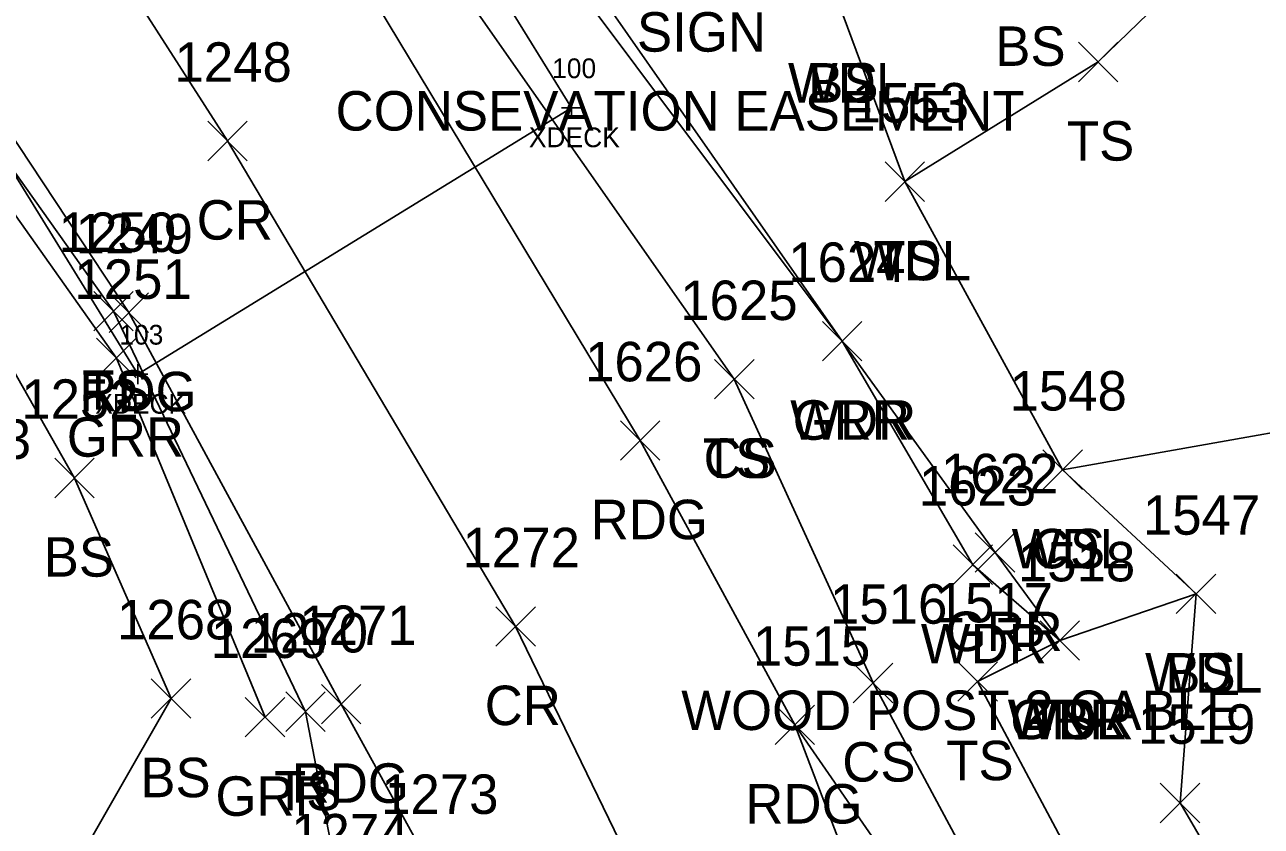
# Model space of a CAD drawing. Extents: x 1469310 to 1475157, y 493997 to 498873.
# Drawn here: x 1469560.4 to 1469623, y 498537.1 to 498577.7 of the extents above; entities that cross this region are included whole.
import ezdxf

# ---------------------------------------------------------------- set-up
doc = ezdxf.new("R2010")
doc.units = 0
for name, color, linetype in [('B_A', 7, 'Continuous'), ('B_I', 7, 'Continuous'), ('B_TIC', 7, 'Continuous'), ('BELB', 7, 'Continuous'), ('L_A', 7, 'Continuous'), ('L_I', 7, 'Continuous'), ('L_TIC', 7, 'Continuous'), ('LAWA', 7, 'Continuous'), ('LELB', 7, 'Continuous'), ('P_A', 7, 'Continuous'), ('P_I', 7, 'Continuous'), ('P_TIC', 7, 'Continuous'), ('PEU', 7, 'Continuous'), ('PRC', 7, 'Continuous'), ('R_A', 7, 'Continuous'), ('R_C', 7, 'Continuous'), ('R_I', 7, 'Continuous'), ('R_TIC', 7, 'Continuous'), ('RGR', 7, 'Continuous'), ('S_A', 7, 'Continuous'), ('S_C', 7, 'Continuous')]:
    doc.layers.add(name, color=color, linetype=linetype)

msp = doc.modelspace()

# ---------------------------------------------------------------- linework, layer by layer
at = {"layer": 'B_TIC'}
for p, q in [((1469588.088, 498573.469), (1469588.164, 498573.469)), ((1469566.108, 498559.964), (1469566.184, 498559.964))]:
    msp.add_line(p, q, dxfattribs=at)
for points in [[(1469587.585, 498573.469), (1469588.585, 498573.469)], [(1469588.085, 498572.969), (1469588.085, 498573.969)], [(1469566.105, 498559.464), (1469566.105, 498560.465)], [(1469565.605, 498559.964), (1469566.605, 498559.964)]]:
    msp.add_lwpolyline(points, dxfattribs=at)
at = {"layer": 'BELB'}
msp.add_lwpolyline([(1469588.085, 498573.469), (1469568.345, 498605.383), (1469546.47, 498591.781), (1469566.105, 498559.964), (1469588.085, 498573.469)], dxfattribs=at)
at = {"layer": 'L_TIC'}
for points in [[(1469613.784, 498574.789), (1469615.784, 498576.789)], [(1469615.784, 498574.789), (1469613.784, 498576.789)], [(1469603.978, 498568.723), (1469605.978, 498570.723)], [(1469605.978, 498568.723), (1469603.978, 498570.723)], [(1469603.978, 498568.723), (1469605.978, 498570.723)], [(1469605.978, 498568.723), (1469603.978, 498570.723)], [(1469563.878, 498562.16), (1469565.878, 498564.16)], [(1469565.878, 498562.16), (1469563.878, 498564.16)], [(1469600.808, 498560.641), (1469602.808, 498562.641)], [(1469602.808, 498560.641), (1469600.808, 498562.641)], [(1469595.337, 498558.709), (1469597.337, 498560.709)], [(1469597.337, 498558.709), (1469595.337, 498560.709)], [(1469595.337, 498558.709), (1469597.337, 498560.709)], [(1469597.337, 498558.709), (1469595.337, 498560.709)], [(1469611.977, 498554.124), (1469613.977, 498556.124)], [(1469613.977, 498554.124), (1469611.977, 498556.124)], [(1469611.977, 498554.124), (1469613.977, 498556.124)], [(1469613.977, 498554.124), (1469611.977, 498556.124)], [(1469561.893, 498553.703), (1469563.893, 498555.703)], [(1469563.893, 498553.703), (1469561.893, 498555.703)], [(1469607.427, 498549.309), (1469609.427, 498551.309)], [(1469609.427, 498549.309), (1469607.427, 498551.309)], [(1469618.738, 498547.83), (1469620.738, 498549.83)], [(1469620.738, 498547.83), (1469618.738, 498549.83)], [(1469618.738, 498547.83), (1469620.738, 498549.83)], [(1469620.738, 498547.83), (1469618.738, 498549.83)], [(1469611.833, 498545.464), (1469613.833, 498547.464)], [(1469613.833, 498545.464), (1469611.833, 498547.464)], [(1469611.833, 498545.464), (1469613.833, 498547.464)], [(1469613.833, 498545.464), (1469611.833, 498547.464)], [(1469611.833, 498545.464), (1469613.833, 498547.464)], [(1469613.833, 498545.464), (1469611.833, 498547.464)], [(1469602.368, 498543.316), (1469604.368, 498545.316)], [(1469604.368, 498543.316), (1469602.368, 498545.316)], [(1469607.669, 498543.385), (1469609.669, 498545.385)], [(1469609.669, 498543.385), (1469607.669, 498545.385)], [(1469566.788, 498542.524), (1469568.788, 498544.524)], [(1469568.788, 498542.524), (1469566.788, 498544.524)], [(1469573.599, 498541.858), (1469575.599, 498543.858)], [(1469575.599, 498541.858), (1469573.599, 498543.858)], [(1469617.927, 498537.232), (1469619.927, 498539.232)], [(1469619.927, 498537.232), (1469617.927, 498539.232)]]:
    msp.add_lwpolyline(points, dxfattribs=at)
at = {"layer": 'LAWA'}
for points in [[(1469612.833, 498546.464), (1469619.738, 498548.83), (1469612.977, 498555.124), (1469604.978, 498569.723), (1469601.64, 498578.733), (1469597.441, 498587.632), (1469591.889, 498597.878), (1469577.982, 498615.263), (1469573.01, 498624.242), (1469561.449, 498616.788)], [(1469612.833, 498546.464), (1469608.427, 498550.309), (1469601.808, 498561.641), (1469582.15, 498589.77), (1469568.417, 498610.17), (1469561.449, 498616.788)]]:
    msp.add_lwpolyline(points, dxfattribs=at)
at = {"layer": 'LELB'}
for points in [[(1469596.337, 498559.709), (1469578.349, 498585.399), (1469563.744, 498607.627), (1469555.371, 498620.368), (1469550.821, 498626.646), (1469541.68, 498637.319), (1469517.52, 498662.002), (1469494.243, 498687.266), (1469477.199, 498705.84), (1469448.358, 498735.299), (1469427.592, 498756.343), (1469413.618, 498771.296), (1469390.023, 498797.181), (1469364.143, 498823.885)], [(1469416.823, 498734.314), (1469446.326, 498703.097), (1469470.885, 498677.648), (1469509.281, 498636.708), (1469524.422, 498615.805), (1469544.375, 498592.02), (1469564.878, 498563.16), (1469574.599, 498542.858), (1469576.567, 498532.675), (1469562.977, 498525.948), (1469548.2, 498517.369), (1469540.614, 498511.222), (1469554.066, 498484.991), (1469566.508, 498459.59)], [(1469413.419, 498730.944), (1469442.517, 498698.703), (1469468.453, 498674.773), (1469500.535, 498635.821), (1469519.003, 498614.534), (1469533.172, 498594.862), (1469544.52, 498587.119), (1469562.893, 498554.703), (1469567.788, 498543.524), (1469559.261, 498528.602), (1469545.395, 498521.66), (1469536.791, 498513.026)], [(1469812.464, 498502.377), (1469771.643, 498507.322), (1469742.885, 498510.086), (1469696.566, 498535.255), (1469676.255, 498550.532), (1469652.996, 498571.738), (1469634.36, 498584.722), (1469625.46, 498586.142), (1469614.784, 498575.789), (1469604.978, 498569.723)], [(1469810.96, 498484.608), (1469774.316, 498494.217), (1469741.099, 498505.67), (1469693.032, 498528.464), (1469673.62, 498546.033), (1469647.104, 498565.825), (1469633.561, 498558.766), (1469612.977, 498555.124)], [(1469633.096, 498503.601), (1469614.184, 498524.16), (1469603.368, 498544.316), (1469596.337, 498559.709)], [(1469788.816, 498394.717), (1469772.488, 498406.102), (1469747.629, 498424.648), (1469713.944, 498449.335), (1469681.325, 498467.824), (1469654.974, 498486.974), (1469638.094, 498508.736), (1469624.13, 498529.309), (1469618.927, 498538.232), (1469619.738, 498548.83)], [(1469787.64, 498392.56), (1469771.327, 498404.285), (1469746.147, 498422.386), (1469712.154, 498445.439), (1469680.508, 498465.063), (1469652.746, 498484.347), (1469633.096, 498503.601), (1469618.233, 498526.441), (1469608.669, 498544.385), (1469612.833, 498546.464)]]:
    msp.add_lwpolyline(points, dxfattribs=at)
at = {"layer": 'P_TIC'}
for points in [[(1469569.656, 498570.785), (1469571.656, 498572.785)], [(1469571.656, 498570.785), (1469569.656, 498572.785)], [(1469564.651, 498562.085), (1469566.651, 498564.085)], [(1469566.651, 498562.085), (1469564.651, 498564.085)], [(1469590.57, 498555.602), (1469592.57, 498557.602)], [(1469592.57, 498555.602), (1469590.57, 498557.602)], [(1469584.254, 498546.179), (1469586.254, 498548.179)], [(1469586.254, 498546.179), (1469584.254, 498548.179)], [(1469575.412, 498542.24), (1469577.412, 498544.24)], [(1469577.412, 498542.24), (1469575.412, 498544.24)], [(1469598.406, 498541.19), (1469600.406, 498543.19)], [(1469600.406, 498541.19), (1469598.406, 498543.19)], [(1469598.406, 498541.19), (1469600.406, 498543.19)], [(1469600.406, 498541.19), (1469598.406, 498543.19)]]:
    msp.add_lwpolyline(points, dxfattribs=at)
at = {"layer": 'PEU'}
for points in [[(1469787.287, 498391.186), (1469770.786, 498403.186), (1469744.942, 498420.511), (1469711.225, 498443.774), (1469680.07, 498463.208), (1469651.576, 498483.407), (1469630.626, 498501.518), (1469612.52, 498523.24), (1469599.406, 498542.19), (1469591.57, 498556.602), (1469575.608, 498583.062), (1469557.307, 498607.493), (1469540.085, 498628.651), (1469536.237, 498634.985), (1469514.981, 498658.506), (1469490.833, 498684.266), (1469472.689, 498702.569), (1469444.888, 498732.157), (1469424.966, 498753.74), (1469411.282, 498767.744), (1469386.832, 498794.065), (1469360.465, 498820.438)], [(1469418.156, 498735.543), (1469447.908, 498704.219), (1469471.825, 498679.031), (1469509.9, 498637.995), (1469529.399, 498614.803), (1469545.139, 498594.127), (1469565.651, 498563.085), (1469576.412, 498543.24), (1469581.129, 498534.677), (1469591.748, 498510.077), (1469602.71, 498485.38), (1469609.033, 498458.441), (1469615.466, 498438.565), (1469621.976, 498404.809), (1469621.719, 498400.421), (1469625.378, 498362.571), (1469626.198, 498333.717)], [(1469637.732, 498433.091), (1469628.78, 498459.194), (1469619.325, 498491.121), (1469611.933, 498509.329), (1469599.406, 498542.19)]]:
    msp.add_lwpolyline(points, dxfattribs=at)
at = {"layer": 'PRC'}
msp.add_lwpolyline([(1469423.494, 498741.591), (1469452.569, 498710.453), (1469477.957, 498685.461), (1469512.008, 498647.602), (1469532.7, 498623.323), (1469554.784, 498596.501), (1469570.656, 498571.785), (1469585.254, 498547.179), (1469603.312, 498509.955), (1469610.701, 498488.938), (1469623.702, 498439.145), (1469630.721, 498407.825), (1469631.037, 498401.913), (1469634.459, 498363.902), (1469634.516, 498333.309)], dxfattribs=at)
at = {"layer": 'R_TIC'}
for points in [[(1469600.808, 498560.641), (1469602.808, 498562.641)], [(1469602.808, 498560.641), (1469600.808, 498562.641)], [(1469564.017, 498559.783), (1469566.017, 498561.783)], [(1469566.017, 498559.783), (1469564.017, 498561.783)], [(1469608.552, 498549.93), (1469610.552, 498551.93)], [(1469610.552, 498549.93), (1469608.552, 498551.93)], [(1469611.833, 498545.464), (1469613.833, 498547.464)], [(1469613.833, 498545.464), (1469611.833, 498547.464)], [(1469571.552, 498541.581), (1469573.552, 498543.581)], [(1469573.552, 498541.581), (1469571.552, 498543.581)]]:
    msp.add_lwpolyline(points, dxfattribs=at)
at = {"layer": 'RGR'}
for points in [[(1469523.975, 498614.546), (1469543.903, 498590.637), (1469565.017, 498560.783), (1469572.552, 498542.581)], [(1469612.833, 498546.464), (1469609.552, 498550.93), (1469601.808, 498561.641), (1469580.889, 498589.56), (1469567.5, 498609.651)]]:
    msp.add_lwpolyline(points, dxfattribs=at)

# ---------------------------------------------------------------- texts
at = {"layer": 'B_A'}
for p in [(1469585.927, 498571.469), (1469563.947, 498557.964)]:
    msp.add_text('XDECK', height=1, dxfattribs=at).set_placement(p)
at = {"layer": 'B_I'}
for s, p in [('100', (1469587.104, 498574.969)), ('103', (1469565.168, 498561.464))]:
    msp.add_text(s, height=1, dxfattribs=at).set_placement(p)
at = {"layer": 'L_A'}
for s, p in [('BS', (1469609.562, 498575.591)), ('WDL', (1469599.057, 498573.733)), ('BS', (1469600.081, 498573.733)), ('TS', (1469613.193, 498570.789)), ('WDL', (1469602.395, 498564.723)), ('TS', (1469603.388, 498564.723)), ('TS', (1469563.287, 498558.16)), ('WDR', (1469599.17, 498556.641)), ('TS', (1469594.746, 498554.709)), ('CS', (1469594.778, 498554.709)), ('CS', (1469611.418, 498550.124)), ('BS', (1469561.334, 498549.703)), ('WDL', (1469610.394, 498550.124)), ('WDR', (1469605.789, 498545.309)), ('WDL', (1469617.155, 498543.83)), ('BS', (1469618.179, 498543.83)), ('WDR', (1469610.195, 498541.464)), ('WDL', (1469610.25, 498541.464)), ('TS', (1469611.243, 498541.464)), ('CS', (1469601.809, 498539.316)), ('TS', (1469607.078, 498539.385)), ('BS', (1469566.229, 498538.524)), ('TS', (1469573.008, 498537.858))]:
    msp.add_text(s, height=2, dxfattribs=at).set_placement(p)
at = {"layer": 'L_I'}
for s, p in [('1553', (1469602.285, 498572.723)), ('1553', (1469602.285, 498572.723)), ('1250', (1469562.098, 498566.16)), ('1624', (1469599.068, 498564.641)), ('1625', (1469593.597, 498562.709)), ('1625', (1469593.597, 498562.709)), ('1252', (1469560.2, 498557.703)), ('1548', (1469610.284, 498558.124)), ('1548', (1469610.284, 498558.124)), ('1253', (1469554.746, 498555.672)), ('1253', (1469554.746, 498555.672)), ('1623', (1469605.687, 498553.309)), ('1547', (1469617.045, 498551.83)), ('1547', (1469617.045, 498551.83)), ('1518', (1469610.707, 498549.464)), ('1518', (1469610.707, 498549.464)), ('1518', (1469610.707, 498549.464)), ('1516', (1469601.187, 498547.316)), ('1517', (1469606.543, 498547.385)), ('1268', (1469565.048, 498546.524)), ('1270', (1469571.82, 498545.858)), ('1519', (1469616.794, 498541.232)), ('1274', (1469573.875, 498535.675))]:
    msp.add_text(s, height=2, dxfattribs=at).set_placement(p)
at = {"layer": 'P_A'}
for s, p in [('CR', (1469569.089, 498566.785)), ('RDG', (1469563.139, 498558.085)), ('RDG', (1469589.058, 498551.602)), ('CR', (1469583.687, 498542.179)), ('RDG', (1469573.901, 498538.24)), ('RDG', (1469596.894, 498537.19)), ('RDG', (1469596.894, 498537.19))]:
    msp.add_text(s, height=2, dxfattribs=at).set_placement(p)
at = {"layer": 'P_I'}
for s, p in [('1248', (1469567.963, 498574.785)), ('1249', (1469562.951, 498566.085)), ('1626', (1469588.775, 498559.602)), ('1272', (1469582.561, 498550.179)), ('1271', (1469574.287, 498546.24)), ('1515', (1469597.28, 498545.19)), ('1515', (1469597.28, 498545.19)), ('1273', (1469578.436, 498537.677))]:
    msp.add_text(s, height=2, dxfattribs=at).set_placement(p)
at = {"layer": 'R_A'}
for p in [(1469599.296, 498556.641), (1469562.506, 498555.783), (1469607.04, 498545.93), (1469610.321, 498541.464), (1469570.04, 498537.581)]:
    msp.add_text('GRR', height=2, dxfattribs=at).set_placement(p)
at = {"layer": 'R_C'}
msp.add_text('WOOD POST 2 CABLE', height=2, dxfattribs=at).set_placement((1469593.647, 498541.93))
at = {"layer": 'R_I'}
for s, p in [('1624', (1469599.068, 498564.641)), ('1251', (1469562.892, 498563.783)), ('1622', (1469606.812, 498553.93)), ('1518', (1469610.707, 498549.464)), ('1269', (1469569.804, 498545.581)), ('1273', (1469578.436, 498537.677))]:
    msp.add_text(s, height=2, dxfattribs=at).set_placement(p)
at = {"layer": 'S_A'}
msp.add_text('SIGN', height=2, dxfattribs=at).set_placement((1469591.404, 498576.312))
at = {"layer": 'S_C'}
msp.add_text('CONSEVATION EASEMENT', height=2, dxfattribs=at).set_placement((1469576.129, 498572.312))

doc.saveas('drawing.dxf')
